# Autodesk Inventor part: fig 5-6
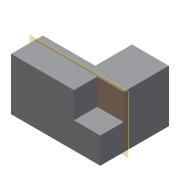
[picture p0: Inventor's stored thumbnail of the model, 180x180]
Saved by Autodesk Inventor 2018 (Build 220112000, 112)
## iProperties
Created: 2010-02
Part Number: fig 5-6
Document SubType Name: Modeling
Designer: CADSoft
Density: 1 g/cm^3
Material: Generic
Appearance: Default
Author: CADSoft
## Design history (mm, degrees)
sketch "Sketch1"
  geometry: L1 (0, 26.227)-(0, 12.145); L2 (0, 12.145)-(-20.026, 12.145); L3 (-20.026, 12.145)-(-20.026, 0); L4 (-20.026, 0)-(14.083, 0); L5 (14.083, 0)-(14.083, 26.227); L6 (14.083, 26.227)-(0, 26.227); 1 further point
  constraints: 12 end point
extrude "Extrusion1" new body sketch "Sketch1" distance "d0" = 20; taper "d1" = 0 deg
sketch "Sketch2"
  geometry: L1 (14.083, 0)-(3.983, 0); L2 (3.983, 0)-(3.983, 8.922); L3 (3.983, 8.922)-(14.083, 8.922); L4 (14.083, 8.922)-(14.083, 0); 1 further point
  constraints: 8 end point
extrude "Extrusion2" cut sketch "Sketch2" distance "d2" = 10; taper "d3" = 0 deg
workplane "Work Plane1"
body "Solid1"
